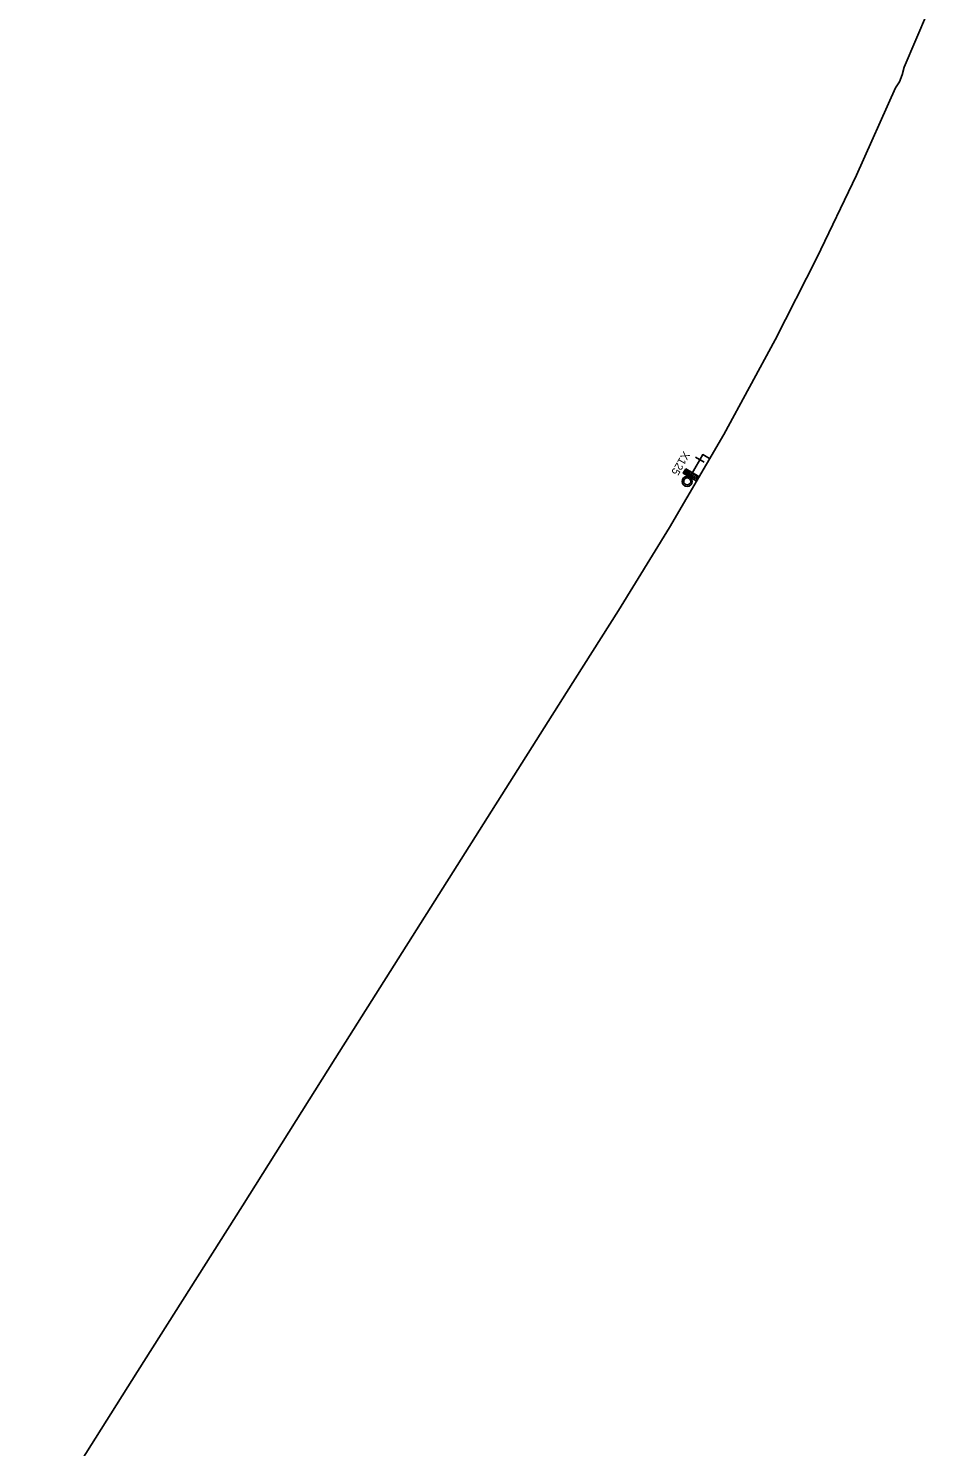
# Model space of a CAD drawing. Extents: x -743359 to -742769, y -1127804 to -1126284.
# Drawn here: x -743125.9 to -742901.3, y -1126992.9 to -1126638.5 of the extents above; entities that cross this region are included whole.
import ezdxf

# ---------------------------------------------------------------- set-up
doc = ezdxf.new("R2010")
doc.units = 0
doc.layers.add('_Zabezpečovací zařízení', color=7, linetype='Continuous')
doc.layers.add('_Zabezpečovací zařízení_trasa', color=7, linetype='Continuous')

msp = doc.modelspace()

# ---------------------------------------------------------------- linework, layer by layer
at = {"layer": '_Zabezpečovací zařízení'}
for p, q in [((-742958.23, -1126746.33), (-742960.75, -1126750.66)), ((-742957.15, -1126746.96), (-742959.31, -1126745.71)), ((-742961.74, -1126748.63), (-742962.37, -1126749.71)), ((-742962.37, -1126749.71), (-742959.13, -1126751.6)), ((-742962.31, -1126749.61), (-742962.27, -1126749.77)), ((-742962.03, -1126749.13), (-742961.79, -1126750.05)), ((-742961.75, -1126748.64), (-742961.3, -1126750.34)), ((-742958.5, -1126750.52), (-742961.74, -1126748.63)), ((-742961.27, -1126748.91), (-742960.82, -1126750.62)), ((-742960.78, -1126749.19), (-742960.51, -1126750.24)), ((-742960.51, -1126750.24), (-742960.33, -1126750.9)), ((-742960.3, -1126749.47), (-742960.22, -1126749.75)), ((-742960.22, -1126749.75), (-742959.85, -1126751.18)), ((-742959.81, -1126749.76), (-742959.36, -1126751.46)), ((-742959.33, -1126750.04), (-742958.98, -1126751.35)), ((-742959.13, -1126751.6), (-742958.5, -1126750.52)), ((-742958.84, -1126750.32), (-742958.7, -1126750.86))]:
    msp.add_line(p, q, dxfattribs=at)
for radius in [1.25, 0.875]:
    msp.add_circle((-742961.38, -1126751.74), radius, dxfattribs=at)
at = {"layer": '_Zabezpečovací zařízení_trasa'}
for points in [[(-742901.32, -1126634.54), (-742907.14, -1126648.25), (-742907.64, -1126650.15), (-742908.37, -1126651.88), (-742909.33, -1126653.4), (-742919.08, -1126675.22), (-742929.03, -1126695.89), (-742939.4, -1126716.38), (-742952.25, -1126740.02), (-742965.82, -1126763.29), (-742978.53, -1126783.97), (-742991.5, -1126804.49), (-743018.82, -1126847.74), (-743049.28, -1126895.95), (-743072.49, -1126932.75), (-743098.65, -1126974.15), (-743125.94, -1127017.38)], [(-742958.23, -1126746.33), (-742957.49, -1126745.05), (-742955.77, -1126746.05)]]:
    msp.add_lwpolyline(points, dxfattribs=at)

# ---------------------------------------------------------------- texts
at = {"layer": '_Zabezpečovací zařízení'}
msp.add_text('X125', height=2, rotation=239.923, dxfattribs=at).set_placement((-742962.3, -1126744.05))

doc.saveas('drawing.dxf')
